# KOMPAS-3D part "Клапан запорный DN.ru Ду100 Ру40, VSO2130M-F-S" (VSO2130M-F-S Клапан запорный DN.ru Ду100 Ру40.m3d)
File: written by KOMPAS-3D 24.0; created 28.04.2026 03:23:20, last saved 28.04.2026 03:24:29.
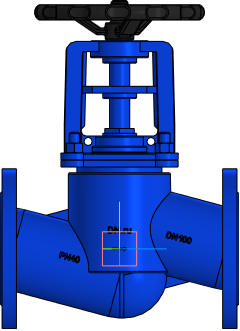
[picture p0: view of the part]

Document properties: Автор: DN.ru; Полное имя файла: C:\Работа\ГОТОВЫЕ ИСХОДНИКИ\VSO2130M-F-S Клапан запорный сильфонный DN.ru Ду15-100 Ру40\DN100\VSO2130M-F-S Клапан запорный DN.ru Ду100 Ру40.m3d

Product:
- Part/product: Клапан запорный DN.ru Ду100 Ру40  | designation VSO2130M-F-S
    Масса: 35
    Раздел спецификации: Прочие изделия
    Примечание: D090-01978

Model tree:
1. Операция без истории:1

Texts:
  VSO2130M-F-S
